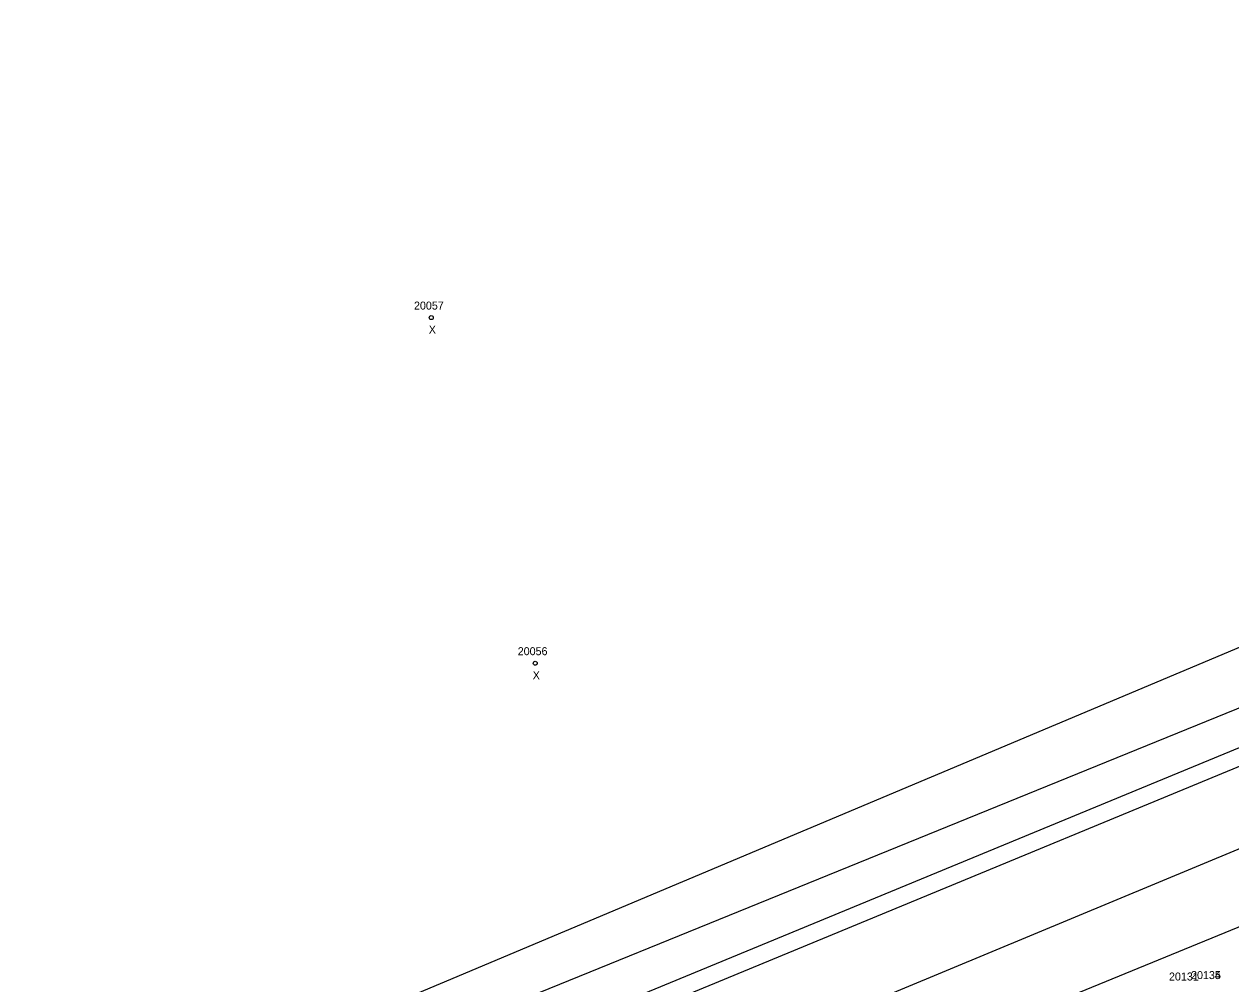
# Model space of a CAD drawing. Extents: x 1966740 to 1969291, y 1117378 to 1118461.
# Drawn here: x 1966891.2 to 1967041.9, y 1117541.5 to 1117661.3 of the extents above; entities that cross this region are included whole.
import ezdxf

# ---------------------------------------------------------------- set-up
doc = ezdxf.new("R2010")
doc.units = 0
for name, color, linetype in [('RD_DTM_BkLn1', 7, 'Continuous'), ('RD_DTM_BkLn2', 7, 'Continuous'), ('RD_EX_H2O', 7, 'Continuous'), ('RD_EX_Road', 7, 'Continuous'), ('RD_SMD_Locator', 7, 'Continuous'), ('RD_SMD_Misc', 7, 'Continuous')]:
    doc.layers.add(name, color=color, linetype=linetype)

msp = doc.modelspace()

# ---------------------------------------------------------------- linework, layer by layer
at = {"layer": 'RD_DTM_BkLn1'}
msp.add_lwpolyline([(1966772.57, 1117449.88), (1966874.49, 1117489.87), (1966974.64, 1117529.93), (1967075.06, 1117571.68), (1967175.91, 1117613.34), (1967274.11, 1117653.69), (1967325.25, 1117674.8), (1967374.73, 1117695), (1967473.9, 1117733.1), (1967569.8, 1117771.9), (1967665.19, 1117809.79), (1967697.89, 1117822.8)], dxfattribs=at)
at = {"layer": 'RD_DTM_BkLn2'}
for points in [[(1966768.15, 1117461.43), (1966869.41, 1117499.34), (1967070.52, 1117582.35), (1967171.25, 1117624.02), (1967269.74, 1117664.9), (1967320.21, 1117685.71), (1967369.37, 1117708.48), (1967468.51, 1117746.66), (1967564.6, 1117784.47), (1967654.68, 1117828.05), (1967680.1, 1117841.48), (1967687.91, 1117842.93), (1967691.45, 1117838.71), (1967693.03, 1117834.22)], [(1966766.42, 1117472.19), (1966865.47, 1117508.82), (1967066.64, 1117593.45), (1967166.55, 1117636.11), (1967264.62, 1117677.56), (1967315.66, 1117698.57), (1967367.9, 1117716.34), (1967464.92, 1117753.87), (1967560.73, 1117793.63)]]:
    msp.add_lwpolyline(points, dxfattribs=at)
at = {"layer": 'RD_EX_H2O'}
msp.add_lwpolyline([(1966766.64, 1117466.58), (1966867.24, 1117504.5), (1967068.76, 1117586.41), (1967167.95, 1117632.67), (1967266.82, 1117671.88), (1967316.79, 1117693.47), (1967368.01, 1117713.34), (1967465.67, 1117751.74), (1967560.73, 1117793.63)], dxfattribs=at)
at = {"layer": 'RD_EX_Road'}
for points in [[(1966769.51, 1117457.48), (1966870.16, 1117497.34), (1966971.19, 1117538.95), (1967071.09, 1117580.24), (1967172.6, 1117621.53), (1967270.79, 1117661.66), (1967321.12, 1117682.57), (1967371.52, 1117702.88), (1967470.26, 1117741.55), (1967566.67, 1117779.5), (1967661.25, 1117817.53), (1967694.4, 1117831.19), (1967697.89, 1117822.8)], [(1966775.75, 1117440.57), (1966876.18, 1117480.39), (1966978.46, 1117522.15), (1967078.26, 1117563.06), (1967180.7, 1117605.06), (1967277.98, 1117644.72), (1967308.82, 1117656.67)]]:
    msp.add_lwpolyline(points, dxfattribs=at)
at = {"layer": 'RD_SMD_Locator'}
for centre in [(1966942.02, 1117624.67), (1966955, 1117581.5)]:
    msp.add_circle(centre, 0.25, dxfattribs=at)

# ---------------------------------------------------------------- texts
at = {"layer": 'RD_SMD_Misc'}
for s, p in [('20057', (1966939.86, 1117625.67)), ('X', (1966941.71, 1117622.67)), ('20056', (1966952.82, 1117582.5)), ('X', (1966954.69, 1117579.5)), ('20131', (1967034.17, 1117541.87)), ('20134', (1967036.93, 1117542.05)), ('20135', (1967036.93, 1117542.05))]:
    msp.add_text(s, height=1, dxfattribs=at).set_placement(p)

doc.saveas('drawing.dxf')
